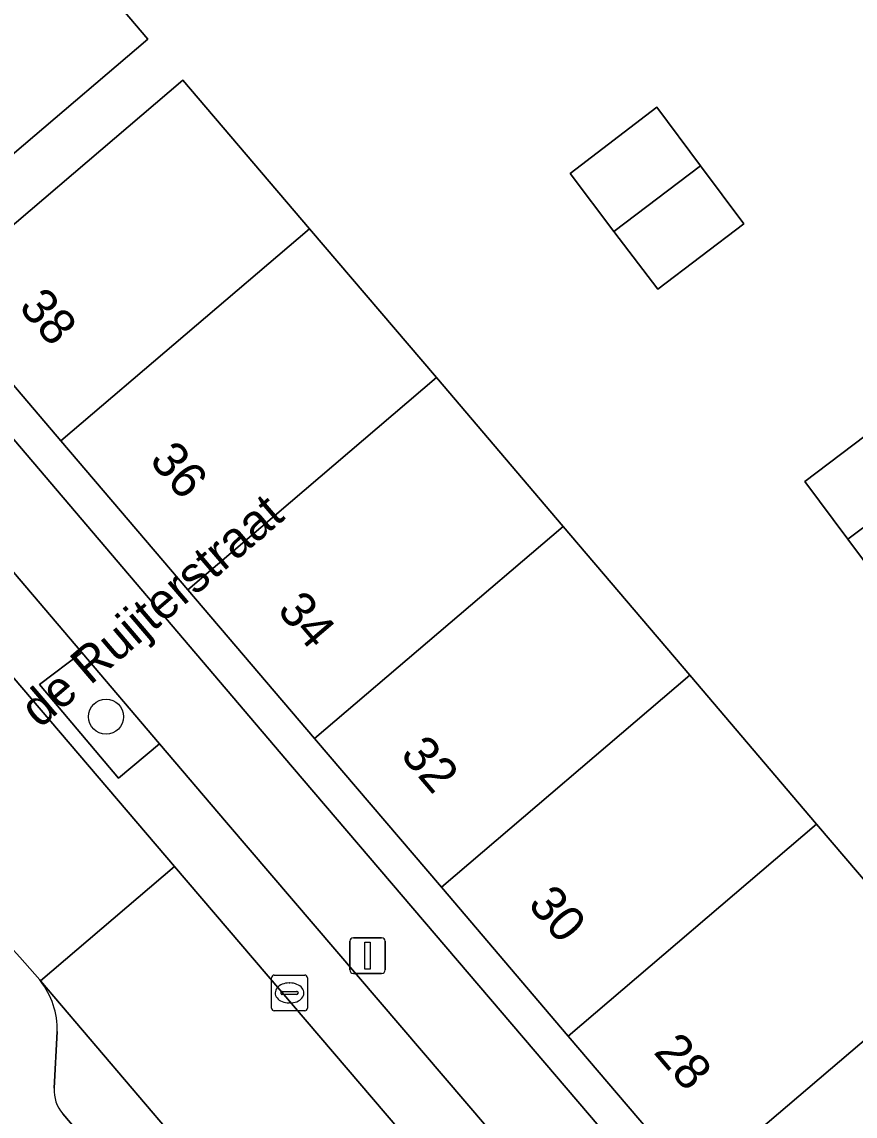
# Model space of a CAD drawing. Extents: x 160377 to 161131, y 383938 to 384853.
# Drawn here: x 160537.01 to 160560.31, y 384619.15 to 384649.73 of the extents above; entities that cross this region are included whole.
import ezdxf

# ---------------------------------------------------------------- set-up
doc = ezdxf.new("R2010")
doc.units = 0
for name, color, linetype in [('IMGEO_Boom', 7, 'Continuous'), ('IMGEO_Erf', 7, 'Continuous'), ('IMGEO_Groenvoorziening', 7, 'Continuous'), ('IMGEO_Kolk', 7, 'Continuous'), ('IMGEO_Lichtmast', 7, 'Continuous'), ('IMGEO_Openbare_ruimte_label', 7, 'Continuous'), ('IMGEO_Pand', 7, 'Continuous'), ('IMGEO_Pand_nummerreeks', 7, 'Continuous'), ('IMGEO_Parkeervlak_open', 7, 'Continuous'), ('IMGEO_Rijbaan_lokaal_open', 7, 'Continuous'), ('IMGEO_Voetpad_open', 7, 'Continuous')]:
    doc.layers.add(name, color=color, linetype=linetype)

msp = doc.modelspace()

# ---------------------------------------------------------------- linework, layer by layer
at = {"layer": 'IMGEO_Boom'}
msp.add_circle((160539.364, 384630.315), 0.489, dxfattribs=at)
at = {"layer": 'IMGEO_Erf'}
for points in [[(160603.494, 384626.95), (160531.839, 384722.221), (160517.199, 384711.18), (160499.817, 384698.107), (160499.831, 384681.477), (160544.574, 384628.905), (160558.691, 384612.377)], [(160555.646, 384617.452), (160552.287, 384621.39), (160548.74, 384625.548), (160545.194, 384629.706), (160541.647, 384633.863), (160538.1, 384638.021), (160534.556, 384642.176), (160533.571, 384643.324), (160530.017, 384647.502), (160526.468, 384651.672), (160522.92, 384655.843), (160519.371, 384660.013), (160515.823, 384664.184), (160512.275, 384668.354), (160508.724, 384672.527), (160500.837, 384681.797), (160500.846, 384687.066), (160500.855, 384692.343), (160500.864, 384697.632), (160510.089, 384704.569)], [(160509.999, 384681.781), (160513.001, 384678.269), (160514.045, 384677.042), (160515.722, 384678.465), (160519.266, 384674.291), (160522.811, 384670.117), (160526.355, 384665.943), (160529.899, 384661.769), (160533.443, 384657.595), (160536.988, 384653.421), (160540.532, 384649.247), (160533.571, 384643.324), (160534.556, 384642.176), (160541.51, 384648.108), (160545.055, 384643.949), (160548.6, 384639.79), (160552.145, 384635.631), (160555.69, 384631.471), (160559.235, 384627.312), (160562.78, 384623.153)]]:
    msp.add_lwpolyline(points, dxfattribs=at)
for points in [[(160554.763, 384647.351), (160555.988, 384645.71), (160557.197, 384644.09), (160554.79, 384642.26), (160553.567, 384643.876), (160552.343, 384645.491)], [(160561.285, 384638.69), (160562.505, 384637.061), (160563.696, 384635.471), (160561.312, 384633.66), (160560.109, 384635.273), (160558.905, 384636.885)]]:
    msp.add_lwpolyline(points, close=True, dxfattribs=at)
at = {"layer": 'IMGEO_Groenvoorziening'}
msp.add_lwpolyline([(160538.686, 384632.106), (160537.505, 384631.216), (160539.713, 384628.595), (160540.854, 384629.561)], close=True, dxfattribs=at)
at = {"layer": 'IMGEO_Kolk'}
for p, q in [((160543.994, 384622.168), (160543.994, 384623.02)), ((160544.069, 384623.094), (160544.921, 384623.094)), ((160544.995, 384623.02), (160544.995, 384622.168)), ((160544.253, 384622.588), (160544.253, 384622.6)), ((160544.296, 384622.637), (160544.694, 384622.637)), ((160544.482, 384622.874), (160544.507, 384622.874)), ((160544.737, 384622.6), (160544.737, 384622.588)), ((160544.691, 384622.551), (160544.293, 384622.551)), ((160544.505, 384622.314), (160544.48, 384622.314)), ((160544.921, 384622.094), (160544.069, 384622.094))]:
    msp.add_line(p, q, dxfattribs=at)
for points in [[(160543.994, 384622.168), (160543.994, 384623.02)], [(160544.069, 384623.094), (160544.921, 384623.094)], [(160544.995, 384623.02), (160544.995, 384622.168)], [(160544.921, 384622.094), (160544.069, 384622.094)]]:
    msp.add_lwpolyline(points, dxfattribs=at)
for centre, radius, start, end in [((160544.071, 384623.018), 0.0765, 91.552, 178.448), ((160544.071, 384623.018), 0.0765, 91.552, 178.448), ((160544.919, 384623.018), 0.0765, 1.552, 88.448), ((160544.919, 384623.018), 0.0765, 1.552, 88.448), ((160544.293, 384622.597), 0.0403, 85.8775, 175.7526), ((160544.29, 384622.587), 0.0366, 178.938, 274.7102), ((160544.694, 384622.594), 0.043, 264.8664, 352.4533), ((160544.698, 384622.599), 0.0386, 1.7309, 96.639), ((160544.071, 384622.17), 0.0765, 181.552, 268.448), ((160544.071, 384622.17), 0.0765, 181.552, 268.448), ((160544.919, 384622.17), 0.0765, 271.552, 358.448), ((160544.919, 384622.17), 0.0765, 271.552, 358.448)]:
    msp.add_arc(centre, radius, start, end, dxfattribs=at)
for centre, major_axis, ratio, start_param, end_param in [((160544.481, 384622.594), (-0.387, 0.002), 0.722429, 4.712389, 7.853982), ((160544.506, 384622.594), (-0.39, 0.002), 0.717154, 1.570796, 4.712389)]:
    msp.add_ellipse(centre, major_axis=major_axis, ratio=ratio, start_param=start_param, end_param=end_param, dxfattribs=at)
at = {"layer": 'IMGEO_Lichtmast'}
for p, q in [((160546.28, 384624.138), (160547.07, 384624.138)), ((160547.07, 384624.138), (160546.28, 384624.138)), ((160546.18, 384623.238), (160546.18, 384624.038)), ((160546.18, 384624.038), (160546.18, 384623.238)), ((160547.17, 384624.038), (160547.17, 384623.238)), ((160547.17, 384623.238), (160547.17, 384624.038)), ((160547.07, 384623.138), (160546.28, 384623.138)), ((160546.28, 384623.138), (160547.07, 384623.138))]:
    msp.add_line(p, q, dxfattribs=at)
msp.add_lwpolyline([(160546.6, 384624.013), (160546.75, 384624.013), (160546.75, 384623.263), (160546.6, 384623.263), (160546.6, 384624.013)], dxfattribs=at)
for centre, start, end in [((160546.28, 384624.038), 90, 180), ((160546.28, 384624.038), 90, 180), ((160547.07, 384624.038), 0, 90), ((160547.07, 384624.038), 360, 90), ((160546.28, 384623.238), 180, 270), ((160546.28, 384623.238), 180, 270), ((160547.07, 384623.238), 270, 0), ((160547.07, 384623.238), 270, 0)]:
    msp.add_arc(centre, 0.1, start, end, dxfattribs=at)
at = {"layer": 'IMGEO_Pand'}
for points in [[(160540.532, 384649.247), (160536.988, 384653.421), (160530.017, 384647.502), (160533.571, 384643.324)], [(160545.055, 384643.949), (160541.51, 384648.108), (160534.556, 384642.176), (160538.1, 384638.021)], [(160552.343, 384645.491), (160553.567, 384643.876), (160555.988, 384645.71), (160554.763, 384647.351)], [(160555.988, 384645.71), (160553.567, 384643.876), (160554.79, 384642.26), (160557.197, 384644.09)], [(160548.6, 384639.79), (160545.055, 384643.949), (160538.1, 384638.021), (160541.647, 384633.863)], [(160552.145, 384635.631), (160548.6, 384639.79), (160541.647, 384633.863), (160545.194, 384629.706)], [(160558.905, 384636.885), (160560.109, 384635.273), (160562.505, 384637.061), (160561.285, 384638.69)], [(160562.505, 384637.061), (160560.109, 384635.273), (160561.312, 384633.66), (160563.696, 384635.471)], [(160555.69, 384631.471), (160552.145, 384635.631), (160545.194, 384629.706), (160548.74, 384625.548)], [(160559.235, 384627.312), (160555.69, 384631.471), (160548.74, 384625.548), (160552.287, 384621.39)], [(160562.78, 384623.153), (160559.235, 384627.312), (160552.287, 384621.39), (160555.646, 384617.452), (160555.833, 384617.232)], [(160566.361, 384618.952), (160566.325, 384618.994), (160562.78, 384623.153), (160555.833, 384617.232), (160556.83, 384616.065), (160559.348, 384613.089), (160559.422, 384613.011), (160559.441, 384613.028)]]:
    msp.add_lwpolyline(points, close=True, dxfattribs=at)
at = {"layer": 'IMGEO_Parkeervlak_open'}
for points in [[(160513.957, 384658.216), (160528.953, 384640.556), (160529.002, 384640.499), (160541.279, 384626.131), (160554.972, 384610.11)], [(160554.483, 384613.622), (160551.084, 384617.595), (160549.965, 384616.678), (160548.944, 384617.832), (160550.055, 384618.797), (160542.733, 384627.355), (160540.854, 384629.561), (160539.713, 384628.595), (160537.505, 384631.216), (160538.686, 384632.106), (160531.621, 384640.401)], [(160538.151, 384619.219), (160544.893, 384611.316), (160546.34, 384612.597), (160537.53, 384622.931)], [(160537.997, 384621.515), (160537.91, 384619.929)]]:
    msp.add_lwpolyline(points, dxfattribs=at)
for centre, radius, start, end in [((160535.797, 384621.574), 2.201, 358.4517, 38.0536), ((160538.937, 384619.882), 1.028, 177.3589, 220.1393)]:
    msp.add_arc(centre, radius, start, end, dxfattribs=at)
at = {"layer": 'IMGEO_Rijbaan_lokaal_open'}
msp.add_lwpolyline([(160536.678, 384623.897), (160536.951, 384623.599), (160537.508, 384622.957), (160537.53, 384622.931), (160541.279, 384626.131), (160529.002, 384640.499)], dxfattribs=at)
msp.add_lwpolyline([(160577.091, 384584.122), (160575.352, 384586.144), (160568.182, 384594.551), (160568.066, 384594.689), (160558.988, 384605.381), (160555.111, 384609.947), (160554.972, 384610.11), (160541.279, 384626.131), (160537.53, 384622.931), (160546.34, 384612.597), (160550.781, 384607.389), (160594.077, 384556.607), (160597.856, 384559.801), (160597.709, 384559.972)], close=True, dxfattribs=at)
at = {"layer": 'IMGEO_Voetpad_open'}
for points in [[(160610.459, 384499.743), (160614.226, 384500.488), (160611.199, 384533.452), (160609.42, 384552.826), (160588.469, 384577.392), (160578.674, 384588.862), (160577.214, 384590.588), (160574.938, 384593.252), (160571.697, 384597.097), (160570.15, 384598.933), (160561.787, 384608.701), (160558.691, 384612.377), (160544.574, 384628.905), (160499.831, 384681.477), (160499.817, 384698.107), (160517.199, 384711.18), (160531.839, 384722.221), (160534.832, 384724.029)], [(160517.141, 384657.401), (160530.592, 384641.609), (160531.621, 384640.401), (160538.686, 384632.106), (160540.854, 384629.561), (160542.733, 384627.355), (160550.055, 384618.797), (160551.084, 384617.595), (160554.483, 384613.622)], [(160537.53, 384622.931), (160537.508, 384622.957), (160536.951, 384623.599), (160536.678, 384623.897)], [(160537.91, 384619.929), (160537.997, 384621.515)], [(160549.373, 384606.064), (160544.893, 384611.316), (160538.151, 384619.219)]]:
    msp.add_lwpolyline(points, dxfattribs=at)
for centre, radius, start, end in [((160535.797, 384621.574), 2.201, 358.4517, 38.0536), ((160538.937, 384619.882), 1.028, 177.3589, 220.1393)]:
    msp.add_arc(centre, radius, start, end, dxfattribs=at)

# ---------------------------------------------------------------- texts
at = {"layer": 'IMGEO_Openbare_ruimte_label'}
msp.add_text('de Ruijterstraat', height=1, rotation=40.5392, dxfattribs=at).set_placement((160537.506, 384629.968))
at = {"layer": 'IMGEO_Pand_nummerreeks'}
for s, p in [('38', (160536.894, 384641.747)), ('36', (160540.549, 384637.462)), ('34', (160544.123, 384633.273)), ('32', (160547.566, 384629.237)), ('30', (160551.132, 384625.056)), ('28', (160554.651, 384620.931))]:
    msp.add_text(s, height=1, rotation=310.4621, dxfattribs=at).set_placement(p)

doc.saveas('drawing.dxf')
